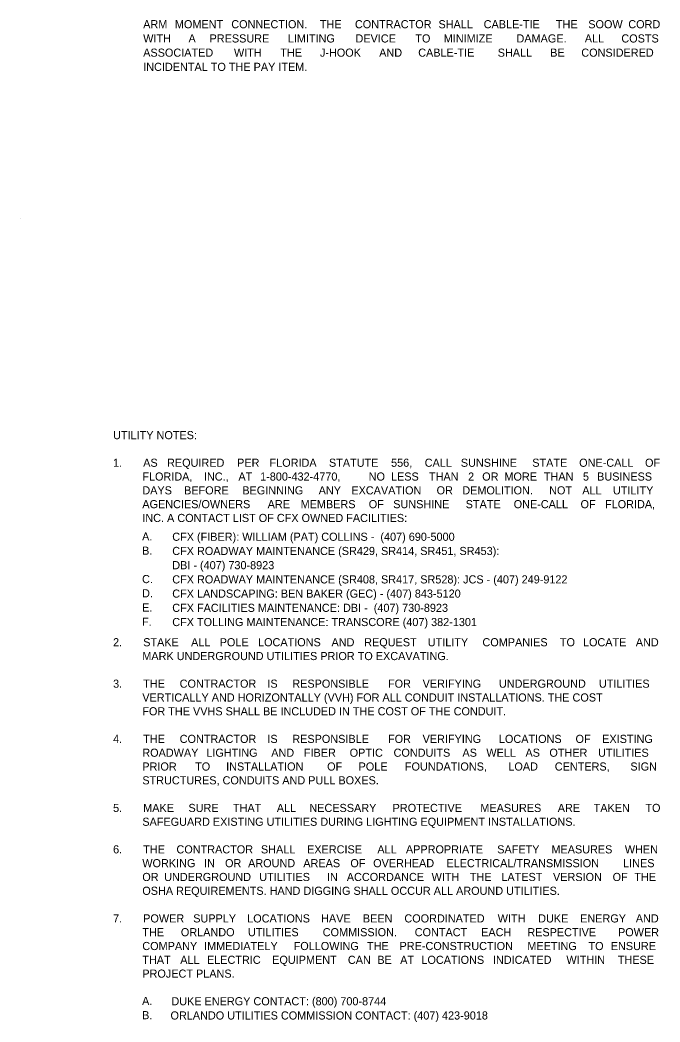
# Model space of a CAD drawing. Extents: x -55 to 2471539, y -90 to 3608906.
# Drawn here: x -54 to 497, y 1664 to 2527 of the extents above; entities that cross this region are included whole.
import ezdxf

# ---------------------------------------------------------------- set-up
doc = ezdxf.new("R2010")
doc.units = 0
doc.layers.add('TextMinor', color=7, linetype='Continuous')
doc.layers.add('XSCell', color=7, linetype='Continuous')

msp = doc.modelspace()

# ---------------------------------------------------------------- linework, layer by layer
at = {"layer": 'TextMinor'}
msp.add_line((-54.3, 2356.32), (-54.3, 2356.32), dxfattribs=at)

# ---------------------------------------------------------------- texts
at = {"layer": 'XSCell'}
for s, p in [('ARM ', (51.88, 2519.99)), ('MOMENT ', (79.21, 2519.99)), ('CONNECTION. ', (127.8, 2519.99)), (' THE ', (201.59, 2519.99)), ('CONTRACTOR ', (234.4, 2519.99)), ('SHALL ', (306.43, 2519.99)), ('CABLE-TIE ', (345.41, 2519.99)), ('THE ', (407.67, 2519.99)), ('SOOW ', (435.57, 2519.99)), ('CORD ', (470.06, 2519.99)), ('WITH ', (51.88, 2507.74)), ('A ', (90.93, 2507.74)), ('PRESSURE ', (109.08, 2507.74)), ('LIMITING ', (176.56, 2507.74)), ('DEVICE ', (234.88, 2507.74)), ('TO ', (286.48, 2507.74)), ('MINIMIZE ', (310.96, 2507.74)), ('DAMAGE. ', (373.67, 2507.74)), (' ALL ', (429.95, 2507.74)), ('COSTS ', (464.09, 2507.74)), ('ASSOCIATED ', (51.88, 2495.49)), ('WITH ', (130.12, 2495.49)), ('THE ', (170.05, 2495.49)), ('J-HOOK ', (204.23, 2495.49)), ('AND ', (255.31, 2495.49)), ('CABLE-TIE ', (288.95, 2495.49)), ('SHALL ', (357.49, 2495.49)), ('BE ', (402.75, 2495.49)), ('CONSIDERED ', (429.56, 2495.49)), ('INCIDENTAL TO THE PAY ITEM.', (51.88, 2483.24)), ('UTILITY NOTES:', (25.93, 2165.88)), ('1.', (25.93, 2142.08)), ('AS ', (51.88, 2142.08)), ('REQUIRED ', (72.45, 2142.08)), ('PER ', (132.84, 2142.08)), ('FLORIDA ', (160.8, 2142.08)), ('STATUTE ', (212.02, 2142.08)), ('556, ', (265.56, 2142.08)), ('CALL ', (294.55, 2142.08)), ('SUNSHINE ', (325.71, 2142.08)), ('STATE ', (387.26, 2142.08)), ('ONE-CALL ', (427.72, 2142.08)), ('OF ', (484.48, 2142.08)), ('FLORIDA, ', (51.12, 2130.18)), ('INC., ', (104.23, 2130.18)), ('AT ', (133.98, 2130.18)), ('1-800-432-4770, ', (152.68, 2130.18)), ('NO ', (246.28, 2130.18)), ('LESS ', (265.49, 2130.18)), ('THAN ', (298.24, 2130.18)), ('2 ', (331.94, 2130.18)), ('OR ', (344.13, 2130.18)), ('MORE ', (363.28, 2130.18)), ('THAN ', (397.29, 2130.18)), ('5 ', (430.99, 2130.18)), ('BUSINESS ', (443.18, 2130.18)), ('DAYS ', (51.12, 2118.28)), ('BEFORE ', (87.13, 2118.28)), ('BEGINNING ', (137.34, 2118.28)), ('ANY ', (203.14, 2118.28)), ('EXCAVATION ', (231.32, 2118.28)), ('OR ', (304.81, 2118.28)), ('DEMOLITION. ', (326.96, 2118.28)), ('NOT ', (401.82, 2118.28)), ('ALL ', (430.4, 2118.28)), ('UTILITY ', (456.81, 2118.28)), ('AGENCIES/OWNERS ', (51.12, 2106.38)), ('ARE ', (159.16, 2106.38)), ('MEMBERS ', (187.58, 2106.38)), ('OF ', (246.33, 2106.38)), ('SUNSHINE ', (267.4, 2106.38)), ('STATE ', (329.87, 2106.38)), ('ONE-CALL ', (371.24, 2106.38)), ('OF ', (428.91, 2106.38)), ('FLORIDA, ', (449.99, 2106.38)), ('INC. A CONTACT LIST OF CFX OWNED FACILITIES:', (51.12, 2094.48)), ('A.', (50.92, 2078.56)), ('CFX (FIBER): WILLIAM (PAT) COLLINS -  (407) 690-5000', (76.93, 2078.29)), ('B.', (50.92, 2066.31)), ('CFX ROADWAY MAINTENANCE (SR429, SR414, SR451, SR453): ', (76.93, 2066.04)), ('DBI - (407) 730-8923', (76.93, 2053.79)), ('C.', (50.92, 2041.81)), ('CFX ROADWAY MAINTENANCE (SR408, SR417, SR528): JCS - (407) 249-9122', (76.93, 2041.54)), ('D.', (50.92, 2029.56)), ('CFX LANDSCAPING: BEN BAKER (GEC) - (407) 843-5120', (76.93, 2029.29)), ('E.', (50.92, 2017.31)), ('CFX FACILITIES MAINTENANCE: DBI -  (407) 730-8923', (76.93, 2017.04)), ('F.', (50.92, 2005.06)), ('CFX TOLLING MAINTENANCE: TRANSCORE (407) 382-1301', (76.93, 2004.79)), ('2.', (25.93, 1987.38)), ('STAKE ', (51.88, 1987.38)), ('ALL ', (93.17, 1987.38)), ('POLE ', (117.82, 1987.38)), ('LOCATIONS ', (150.88, 1987.38)), ('AND ', (214.2, 1987.38)), ('REQUEST ', (242.38, 1987.38)), ('UTILITY ', (297.2, 1987.38)), ('COMPANIES ', (344.33, 1987.38)), ('TO ', (411.09, 1987.38)), ('LOCATE ', (430.98, 1987.38)), ('AND ', (476.52, 1987.38)), ('MARK UNDERGROUND UTILITIES PRIOR TO EXCAVATING.', (51.12, 1975.48)), ('3.', (25.93, 1951.68)), ('THE ', (51.88, 1951.68)), ('CONTRACTOR ', (83.33, 1951.68)), ('IS ', (158.93, 1951.68)), ('RESPONSIBLE ', (180.41, 1951.68)), ('FOR ', (262.92, 1951.68)), ('VERIFYING ', (292.77, 1951.68)), ('UNDERGROUND ', (358.54, 1951.68)), ('UTILITIES ', (444.75, 1951.68)), ('VERTICALLY AND HORIZONTALLY (VVH) FOR ALL CONDUIT INSTALLATIONS. THE COST ', (51.12, 1939.78)), ('FOR THE VVHS SHALL BE INCLUDED IN THE COST OF THE CONDUIT.', (51.12, 1927.88)), ('4.', (25.93, 1904.08)), ('THE ', (51.88, 1904.08)), ('CONTRACTOR ', (83.33, 1904.08)), ('IS ', (158.92, 1904.08)), ('RESPONSIBLE ', (180.4, 1904.08)), ('FOR ', (262.91, 1904.08)), ('VERIFYING ', (292.75, 1904.08)), ('LOCATIONS ', (358.52, 1904.08)), ('OF ', (424.58, 1904.08)), ('EXISTING ', (447.54, 1904.08)), ('ROADWAY ', (51.12, 1892.18)), ('LIGHTING ', (106.3, 1892.18)), ('AND ', (162.24, 1892.18)), ('FIBER ', (190.41, 1892.18)), ('OPTIC ', (229.87, 1892.18)), ('CONDUITS ', (267.7, 1892.18)), ('AS ', (327.08, 1892.18)), ('WELL ', (347.7, 1892.18)), ('AS ', (381.42, 1892.18)), ('OTHER ', (402.04, 1892.18)), ('UTILITIES ', (444, 1892.18)), ('PRIOR ', (51.12, 1880.28)), ('TO ', (96.64, 1880.28)), ('INSTALLATION ', (123.39, 1880.28)), ('OF ', (210.46, 1880.28)), ('POLE ', (237.55, 1880.28)), ('FOUNDATIONS, ', (277.47, 1880.28)), ('LOAD ', (366.67, 1880.28)), ('CENTERS, ', (406.69, 1880.28)), ('SIGN ', (471.85, 1880.28)), ('STRUCTURES, CONDUITS AND PULL BOXES.', (51.12, 1868.38)), ('5.', (25.93, 1844.58)), ('MAKE ', (51.88, 1844.58)), ('SURE ', (90.88, 1844.58)), ('THAT ', (129.25, 1844.58)), ('ALL ', (167.06, 1844.58)), ('NECESSARY ', (195.14, 1844.58)), ('PROTECTIVE ', (266.87, 1844.58)), ('MEASURES ', (342.5, 1844.58)), ('ARE ', (409.22, 1844.58)), ('TAKEN ', (440.22, 1844.58)), ('TO ', (484.81, 1844.58)), ('SAFEGUARD EXISTING UTILITIES DURING LIGHTING EQUIPMENT INSTALLATIONS.', (51.12, 1832.68)), ('6.', (25.93, 1808.88)), ('THE ', (51.88, 1808.88)), ('CONTRACTOR ', (80.56, 1808.88)), ('SHALL ', (153.39, 1808.88)), ('EXERCISE ', (193.15, 1808.88)), ('ALL ', (253.73, 1808.88)), ('APPROPRIATE ', (278.35, 1808.88)), ('SAFETY ', (357.05, 1808.88)), ('MEASURES ', (403.81, 1808.88)), ('WHEN ', (467.07, 1808.88)), ('WORKING ', (51.12, 1796.98)), ('IN ', (104.36, 1796.98)), ('OR ', (122.44, 1796.98)), ('AROUND ', (142.3, 1796.98)), ('AREAS ', (189.9, 1796.98)), ('OF ', (230.43, 1796.98)), ('OVERHEAD ', (250.13, 1796.98)), ('ELECTRICAL/TRANSMISSION ', (313.25, 1796.98)), ('LINES ', (465.57, 1796.98)), ('OR ', (51.12, 1785.08)), ('UNDERGROUND ', (69.97, 1785.08)), ('UTILITIES ', (151.91, 1785.08)), ('IN ', (210.32, 1785.08)), ('ACCORDANCE ', (227.4, 1785.08)), ('WITH ', (300.52, 1785.08)), ('THE ', (333.46, 1785.08)), ('LATEST ', (360.64, 1785.08)), ('VERSION ', (405.17, 1785.08)), ('OF ', (456.54, 1785.08)), ('THE ', (475.23, 1785.08)), ('OSHA REQUIREMENTS. HAND DIGGING SHALL OCCUR ALL AROUND UTILITIES.', (51.12, 1773.18)), ('7.', (25.93, 1749.38)), ('POWER ', (51.88, 1749.38)), ('SUPPLY ', (95, 1749.38)), ('LOCATIONS ', (141.53, 1749.38)), ('HAVE ', (205.24, 1749.38)), ('BEEN ', (241.22, 1749.38)), ('COORDINATED ', (277.03, 1749.38)), ('WITH ', (357.5, 1749.38)), ('DUKE ', (392.36, 1749.38)), ('ENERGY ', (428.57, 1749.38)), ('AND ', (476.52, 1749.38)), ('THE ', (51.12, 1737.48)), ('ORLANDO ', (84.35, 1737.48)), ('UTILITIES ', (142.2, 1737.48)), ('COMMISSION. ', (206.65, 1737.48)), ('CONTACT ', (285.96, 1737.48)), ('EACH ', (343.21, 1737.48)), ('RESPECTIVE ', (383.03, 1737.48)), ('POWER ', (461.2, 1737.48)), ('COMPANY ', (51.12, 1725.58)), ('IMMEDIATELY ', (104.38, 1725.58)), ('FOLLOWING ', (181.58, 1725.58)), ('THE ', (244.82, 1725.58)), ('PRE-CONSTRUCTION ', (272.86, 1725.58)), ('MEETING ', (383.03, 1725.58)), ('TO ', (435.74, 1725.58)), ('ENSURE ', (454.94, 1725.58)), ('THAT ', (51.12, 1713.68)), ('ALL ', (83.84, 1713.68)), ('ELECTRIC ', (106.84, 1713.68)), ('EQUIPMENT ', (163.06, 1713.68)), ('CAN ', (228.33, 1713.68)), ('BE ', (253.73, 1713.68)), ('AT ', (273.43, 1713.68)), ('LOCATIONS ', (291.71, 1713.68)), ('INDICATED ', (353.38, 1713.68)), ('WITHIN ', (416.73, 1713.68)), ('THESE ', (461.02, 1713.68)), ('PROJECT PLANS.', (51.12, 1701.78)), ('A.', (50.92, 1678.25)), ('DUKE ENERGY CONTACT: (800) 700-8744', (76.18, 1677.98)), ('B.', (50.92, 1666)), ('ORLANDO UTILITIES COMMISSION CONTACT: (407) 423-9018', (75.42, 1665.73))]:
    msp.add_text(s, height=7, dxfattribs=at).set_placement(p)

doc.saveas('drawing.dxf')
